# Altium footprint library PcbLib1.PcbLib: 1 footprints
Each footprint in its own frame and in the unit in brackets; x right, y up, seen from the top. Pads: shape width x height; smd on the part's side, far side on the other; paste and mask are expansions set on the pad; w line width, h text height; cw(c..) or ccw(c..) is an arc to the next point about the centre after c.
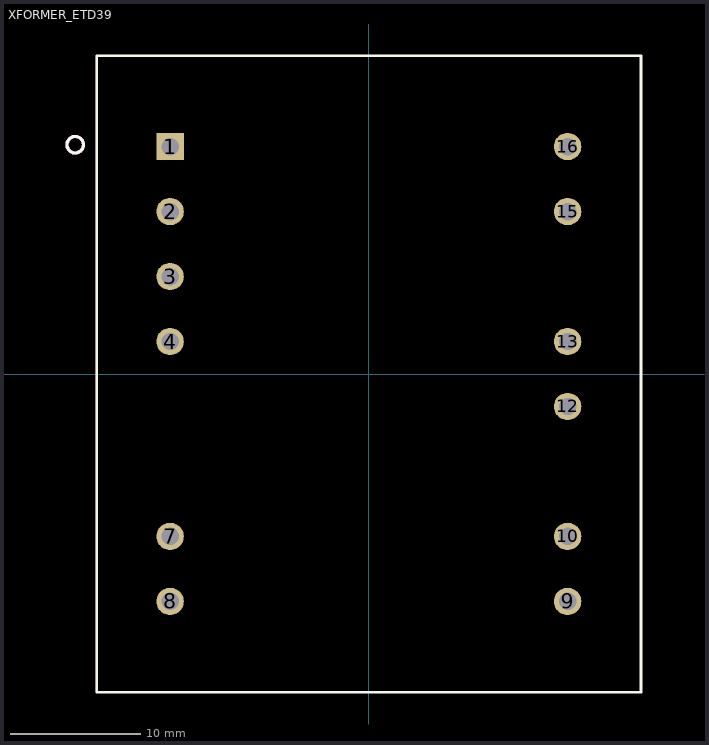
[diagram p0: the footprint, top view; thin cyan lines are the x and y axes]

## XFORMER_ETD39 [mil]
height 1299
pads (12):
  rect 83x83 hole 53: 1(-602.5,689.5)
  round 83 hole 53: 2(-602.5,492.5) 3(-602.5,295.5) 4(-602.5,98.5) 7(-602.5,-492.5) 8(-602.5,-689.5) 9(602.5,-689.5) 10(602.5,-492.5) 12(602.5,-98.5) 13(602.5,98.5) 15(602.5,492.5) 16(602.5,689.5)
Top Overlay:
  circle w10: c-890,695 r25
  lines w7.87: -825,-964.5 825,-964.5 825,964.5 -825,964.5 -825,-964.5
Mechanical 5:
  circle w10: c-890,695 r25
  lines w6: -825,-964.5 -825,964.5 825,964.5 825,-964.5 -825,-964.5
  text ".Designator" at -215,20 h40
3D body: height 1299, standoff 150, extent -825,-964.5 825,964.5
